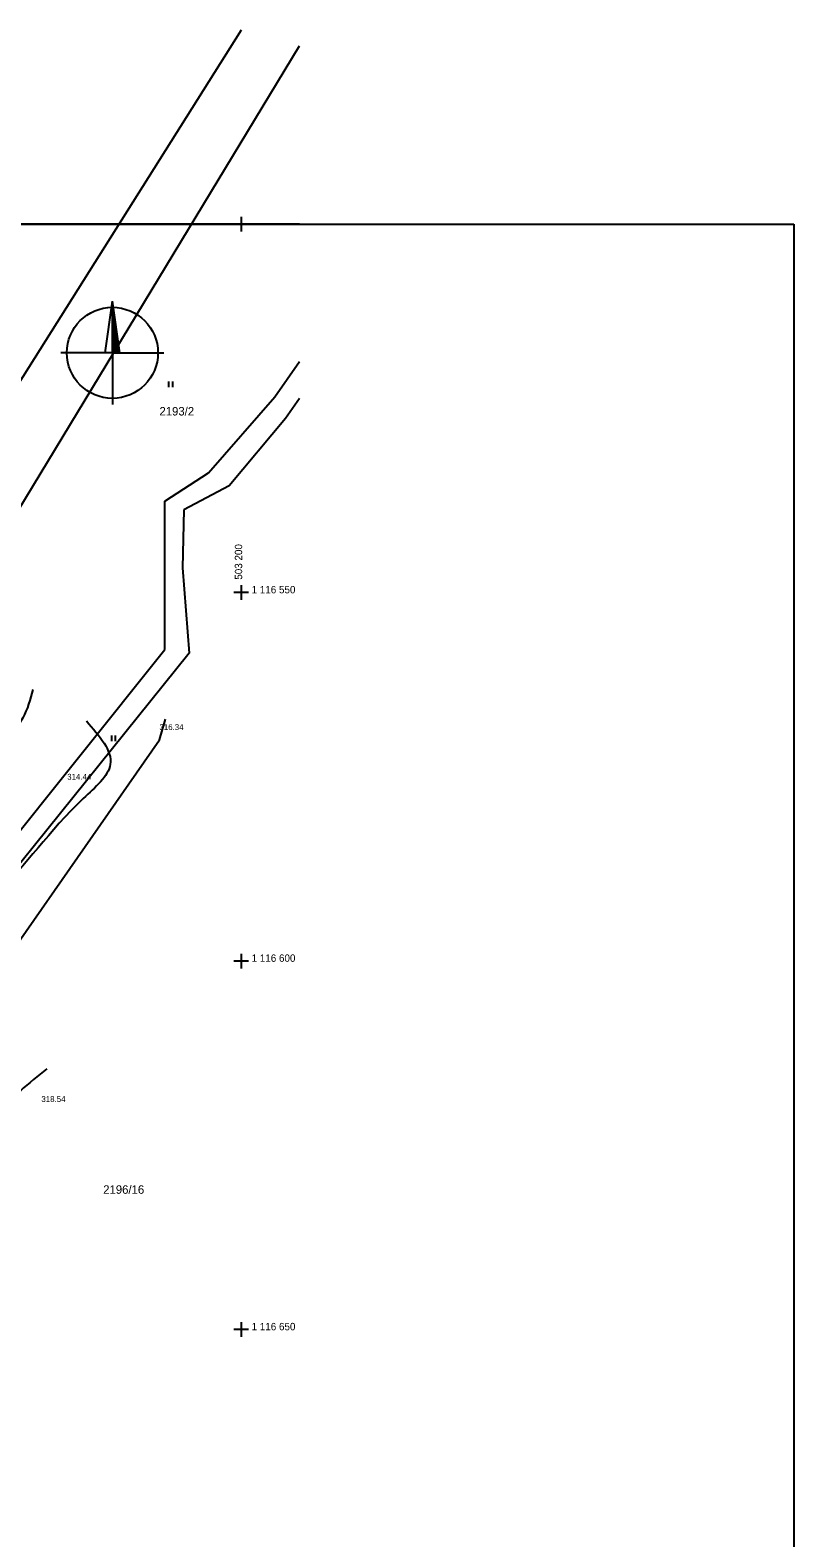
# Model space of a CAD drawing. Extents: x -504375 to -503125, y -1118000 to -1116474.
# Drawn here: x -503228.6 to -503125, y -1116678.3 to -1116473.7 of the extents above; entities that cross this region are included whole.
import ezdxf

# ---------------------------------------------------------------- set-up
doc = ezdxf.new("R2010")
doc.units = 0
for name, color, linetype in [('Druhy povrchů', 7, 'Continuous'), ('Podkladové mapy', 7, 'Continuous'), ('Síť dekadická', 7, 'Continuous'), ('Vrstva 34', 7, 'Continuous'), ('Vrstva 48', 7, 'Continuous'), ('Výšky bodů plotr', 7, 'Continuous')]:
    doc.layers.add(name, color=color, linetype=linetype)

msp = doc.modelspace()

# ---------------------------------------------------------------- linework, layer by layer
at = {"layer": 'Druhy povrchů'}
for p, q in [((-503217.54, -1116570.142), (-503217.54, -1116569.392)), ((-503217.04, -1116570.142), (-503217.04, -1116569.392))]:
    msp.add_line(p, q, dxfattribs=at)
at = {"layer": 'Podkladové mapy'}
for p, q in [((-503200.022, -1116473.684), (-503238.29, -1116534.46)), ((-503230.27, -1116538.88), (-503192.069, -1116475.796)), ((-503195.45, -1116523.45), (-503192.069, -1116518.634)), ((-503209.807, -1116522.114), (-503209.807, -1116521.364)), ((-503209.307, -1116521.364), (-503209.307, -1116522.114)), ((-503204.44, -1116533.76), (-503195.45, -1116523.45)), ((-503192.069, -1116523.684), (-503193.98, -1116526.4)), ((-503193.98, -1116526.4), (-503201.65, -1116535.51)), ((-503210.38, -1116537.61), (-503204.44, -1116533.76)), ((-503201.65, -1116535.51), (-503207.78, -1116538.78)), ((-503210.38, -1116557.71), (-503210.38, -1116537.61)), ((-503207.78, -1116538.78), (-503207.98, -1116546.65)), ((-503207.98, -1116546.65), (-503207.06, -1116558.21)), ((-503233.98, -1116587.25), (-503210.38, -1116557.71)), ((-503207.06, -1116558.21), (-503233.96, -1116591.65))]:
    msp.add_line(p, q, dxfattribs=at)
at = {"layer": 'Síť dekadická'}
msp.add_lwpolyline([(-503125, -1116500), (-503125, -1117000), (-503750, -1117000), (-503750, -1116500)], close=True, dxfattribs=at)
at = {"layer": 'Vrstva 34'}
for p, q in [((-503200, -1116499), (-503200, -1116501)), ((-503199, -1116500), (-503201, -1116500)), ((-503218.473, -1116517.471), (-503217.473, -1116510.471)), ((-503216.473, -1116517.471), (-503217.473, -1116510.471)), ((-503217.473, -1116517.471), (-503217.473, -1116510.471)), ((-503217.473, -1116510.515), (-503217.467, -1116510.515)), ((-503217.473, -1116510.565), (-503217.459, -1116510.565)), ((-503217.473, -1116510.615), (-503217.452, -1116510.615)), ((-503217.473, -1116510.665), (-503217.445, -1116510.665)), ((-503217.473, -1116510.715), (-503217.438, -1116510.715)), ((-503217.473, -1116510.765), (-503217.431, -1116510.765)), ((-503217.473, -1116510.815), (-503217.424, -1116510.815)), ((-503217.473, -1116510.865), (-503217.417, -1116510.865)), ((-503217.473, -1116510.915), (-503217.41, -1116510.915)), ((-503217.473, -1116510.965), (-503217.402, -1116510.965)), ((-503217.473, -1116511.015), (-503217.395, -1116511.015)), ((-503217.473, -1116511.065), (-503217.388, -1116511.065)), ((-503217.473, -1116511.115), (-503217.381, -1116511.115)), ((-503217.473, -1116511.165), (-503217.374, -1116511.165)), ((-503217.473, -1116511.215), (-503217.367, -1116511.215)), ((-503217.473, -1116511.265), (-503217.36, -1116511.265)), ((-503217.473, -1116511.325), (-503217.351, -1116511.325)), ((-503217.473, -1116511.375), (-503217.344, -1116511.375)), ((-503217.473, -1116511.425), (-503217.337, -1116511.425)), ((-503217.473, -1116511.475), (-503217.33, -1116511.475)), ((-503217.473, -1116511.525), (-503217.323, -1116511.525)), ((-503217.473, -1116511.575), (-503217.315, -1116511.575)), ((-503217.473, -1116511.625), (-503217.308, -1116511.625)), ((-503217.473, -1116511.675), (-503217.301, -1116511.675)), ((-503217.473, -1116511.725), (-503217.294, -1116511.725)), ((-503217.473, -1116511.775), (-503217.287, -1116511.775)), ((-503217.473, -1116511.825), (-503217.28, -1116511.825)), ((-503217.473, -1116511.875), (-503217.273, -1116511.875)), ((-503217.473, -1116511.925), (-503217.265, -1116511.925)), ((-503217.473, -1116511.975), (-503217.258, -1116511.975)), ((-503217.473, -1116512.025), (-503217.251, -1116512.025)), ((-503217.473, -1116512.075), (-503217.244, -1116512.075)), ((-503217.473, -1116512.125), (-503217.237, -1116512.125)), ((-503217.473, -1116512.175), (-503217.23, -1116512.175)), ((-503217.473, -1116512.225), (-503217.223, -1116512.225)), ((-503217.473, -1116512.275), (-503217.215, -1116512.275)), ((-503217.473, -1116512.325), (-503217.208, -1116512.325)), ((-503217.473, -1116512.375), (-503217.201, -1116512.375)), ((-503217.473, -1116512.425), (-503217.194, -1116512.425)), ((-503217.473, -1116512.475), (-503217.187, -1116512.475)), ((-503217.473, -1116512.525), (-503217.18, -1116512.525)), ((-503217.473, -1116512.575), (-503217.173, -1116512.575)), ((-503217.473, -1116512.625), (-503217.165, -1116512.625)), ((-503217.473, -1116512.675), (-503217.158, -1116512.675)), ((-503217.473, -1116512.725), (-503217.151, -1116512.725)), ((-503217.473, -1116512.775), (-503217.144, -1116512.775)), ((-503217.473, -1116512.825), (-503217.137, -1116512.825)), ((-503217.473, -1116512.875), (-503217.13, -1116512.875)), ((-503217.473, -1116512.925), (-503217.122, -1116512.925)), ((-503217.473, -1116512.975), (-503217.115, -1116512.975)), ((-503217.473, -1116513.025), (-503217.108, -1116513.025)), ((-503217.473, -1116513.075), (-503217.101, -1116513.075)), ((-503217.473, -1116513.125), (-503217.094, -1116513.125)), ((-503217.473, -1116513.175), (-503217.087, -1116513.175)), ((-503217.473, -1116513.225), (-503217.08, -1116513.225)), ((-503217.473, -1116513.275), (-503217.072, -1116513.275)), ((-503217.473, -1116513.325), (-503217.065, -1116513.325)), ((-503217.473, -1116513.375), (-503217.058, -1116513.375)), ((-503217.473, -1116513.425), (-503217.051, -1116513.425)), ((-503217.473, -1116513.475), (-503217.044, -1116513.475)), ((-503217.473, -1116513.525), (-503217.037, -1116513.525)), ((-503217.473, -1116513.575), (-503217.03, -1116513.575)), ((-503217.473, -1116513.625), (-503217.022, -1116513.625)), ((-503217.473, -1116513.675), (-503217.015, -1116513.675)), ((-503217.473, -1116513.725), (-503217.008, -1116513.725)), ((-503217.473, -1116513.775), (-503217.001, -1116513.775)), ((-503217.473, -1116513.825), (-503216.994, -1116513.825)), ((-503217.473, -1116513.875), (-503216.987, -1116513.875)), ((-503217.473, -1116513.925), (-503216.98, -1116513.925)), ((-503217.473, -1116513.975), (-503216.972, -1116513.975)), ((-503217.473, -1116514.025), (-503216.965, -1116514.025)), ((-503217.473, -1116514.075), (-503216.958, -1116514.075)), ((-503217.473, -1116514.125), (-503216.951, -1116514.125)), ((-503217.473, -1116514.175), (-503216.944, -1116514.175)), ((-503217.473, -1116514.225), (-503216.937, -1116514.225)), ((-503217.473, -1116514.275), (-503216.93, -1116514.275)), ((-503217.473, -1116514.325), (-503216.922, -1116514.325)), ((-503217.473, -1116514.375), (-503216.915, -1116514.375)), ((-503217.473, -1116514.425), (-503216.908, -1116514.425)), ((-503217.473, -1116514.475), (-503216.901, -1116514.475)), ((-503217.473, -1116514.525), (-503216.894, -1116514.525)), ((-503217.473, -1116514.575), (-503216.887, -1116514.575)), ((-503217.473, -1116514.625), (-503216.88, -1116514.625)), ((-503217.473, -1116514.675), (-503216.872, -1116514.675)), ((-503217.473, -1116514.725), (-503216.865, -1116514.725)), ((-503217.473, -1116514.775), (-503216.858, -1116514.775)), ((-503217.473, -1116514.825), (-503216.851, -1116514.825)), ((-503217.473, -1116514.875), (-503216.844, -1116514.875)), ((-503217.473, -1116514.925), (-503216.837, -1116514.925)), ((-503217.473, -1116514.975), (-503216.83, -1116514.975)), ((-503217.473, -1116515.025), (-503216.822, -1116515.025)), ((-503217.473, -1116515.075), (-503216.815, -1116515.075)), ((-503217.473, -1116515.125), (-503216.808, -1116515.125)), ((-503217.473, -1116515.175), (-503216.801, -1116515.175)), ((-503217.473, -1116515.225), (-503216.794, -1116515.225)), ((-503217.473, -1116515.275), (-503216.787, -1116515.275)), ((-503217.473, -1116515.325), (-503216.78, -1116515.325)), ((-503217.473, -1116515.375), (-503216.772, -1116515.375)), ((-503217.473, -1116515.425), (-503216.765, -1116515.425)), ((-503217.473, -1116515.475), (-503216.758, -1116515.475)), ((-503217.473, -1116515.525), (-503216.751, -1116515.525)), ((-503217.473, -1116515.575), (-503216.744, -1116515.575)), ((-503217.473, -1116515.625), (-503216.737, -1116515.625)), ((-503217.473, -1116515.675), (-503216.73, -1116515.675)), ((-503217.473, -1116515.725), (-503216.722, -1116515.725)), ((-503217.473, -1116515.775), (-503216.715, -1116515.775)), ((-503217.473, -1116515.825), (-503216.708, -1116515.825)), ((-503217.473, -1116515.875), (-503216.701, -1116515.875)), ((-503217.473, -1116515.925), (-503216.694, -1116515.925)), ((-503217.473, -1116515.975), (-503216.687, -1116515.975)), ((-503217.473, -1116516.025), (-503216.679, -1116516.025)), ((-503217.473, -1116516.075), (-503216.672, -1116516.075)), ((-503217.473, -1116516.125), (-503216.665, -1116516.125)), ((-503217.473, -1116516.175), (-503216.658, -1116516.175)), ((-503217.473, -1116516.225), (-503216.651, -1116516.225)), ((-503217.473, -1116516.275), (-503216.644, -1116516.275)), ((-503217.473, -1116517.471), (-503224.473, -1116517.471)), ((-503217.473, -1116516.325), (-503216.637, -1116516.325)), ((-503217.473, -1116516.375), (-503216.629, -1116516.375)), ((-503217.473, -1116516.425), (-503216.622, -1116516.425)), ((-503217.473, -1116516.475), (-503216.615, -1116516.475)), ((-503217.473, -1116516.525), (-503216.608, -1116516.525)), ((-503217.473, -1116516.575), (-503216.601, -1116516.575)), ((-503217.473, -1116516.625), (-503216.594, -1116516.625)), ((-503217.473, -1116516.675), (-503216.587, -1116516.675)), ((-503217.473, -1116516.725), (-503216.579, -1116516.725)), ((-503217.473, -1116516.775), (-503216.572, -1116516.775)), ((-503217.473, -1116516.825), (-503216.565, -1116516.825)), ((-503217.473, -1116516.875), (-503216.558, -1116516.875)), ((-503217.473, -1116516.925), (-503216.551, -1116516.925)), ((-503217.473, -1116516.975), (-503216.544, -1116516.975)), ((-503217.473, -1116517.025), (-503216.537, -1116517.025)), ((-503217.473, -1116517.075), (-503216.529, -1116517.075)), ((-503217.473, -1116517.125), (-503216.522, -1116517.125)), ((-503217.473, -1116517.175), (-503216.515, -1116517.175)), ((-503217.473, -1116517.225), (-503216.508, -1116517.225)), ((-503217.473, -1116517.275), (-503216.501, -1116517.275)), ((-503217.473, -1116517.325), (-503216.494, -1116517.325)), ((-503217.473, -1116517.375), (-503216.487, -1116517.375)), ((-503217.473, -1116517.425), (-503216.479, -1116517.425)), ((-503217.473, -1116517.471), (-503217.473, -1116524.471)), ((-503217.473, -1116517.471), (-503216.473, -1116517.471)), ((-503216.473, -1116517.471), (-503210.473, -1116517.471)), ((-503200, -1116549), (-503200, -1116551)), ((-503199, -1116550), (-503201, -1116550)), ((-503199, -1116600), (-503201, -1116600)), ((-503200, -1116599), (-503200, -1116601)), ((-503200, -1116649), (-503200, -1116651)), ((-503199, -1116650), (-503201, -1116650))]:
    msp.add_line(p, q, dxfattribs=at)
msp.add_lwpolyline([(-503192.069, -1116500), (-503591.069, -1116500)], dxfattribs=at)
msp.add_circle((-503217.473, -1116517.47), 6.18, dxfattribs=at)
at = {"layer": 'Vrstva 48'}
msp.add_lwpolyline([(-503300.434, -1116681.166), (-503296.556, -1116668.103), (-503294.8, -1116667.049), (-503286.048, -1116656.931), (-503285.304, -1116656.071), (-503279.91, -1116655.384), (-503275.719, -1116650.391), (-503271.777, -1116639.009), (-503265.04, -1116633.168), (-503262.143, -1116630.656), (-503250.15, -1116616.106), (-503234.98, -1116601.014), (-503231.273, -1116598.925), (-503211.098, -1116569.991), (-503210.256, -1116567.168)], dxfattribs=at)
for points in [[(-503228.261, -1116563.145), (-503229.645, -1116567.016), (-503233.265, -1116571.228), (-503245.688, -1116584.541), (-503247.935, -1116586.867), (-503252.973, -1116594.854), (-503254.135, -1116607.338), (-503261.55, -1116616.428), (-503262.857, -1116617.898), (-503273.652, -1116628.941), (-503288.12, -1116641.769), (-503294.834, -1116647.413), (-503299.542, -1116653.756), (-503302.433, -1116657.068), (-503311.897, -1116663.915), (-503313.227, -1116667.667), (-503316.736, -1116674.505), (-503325.627, -1116690.3), (-503328.511, -1116695.009), (-503335.94, -1116707.278), (-503351.034, -1116723.382), (-503365.126, -1116737.245), (-503372.674, -1116748.782), (-503373.925, -1116753.16), (-503378.551, -1116760.666), (-503382.552, -1116767.547), (-503390.579, -1116780.739), (-503398.79, -1116793.818), (-503400.908, -1116797.881), (-503402.495, -1116807.226), (-503404.198, -1116812.046), (-503412.471, -1116822.312), (-503418.387, -1116829.995), (-503420.024, -1116835.788), (-503425.814, -1116843.155), (-503430.336, -1116857.921), (-503433.683, -1116863.223), (-503434.674, -1116865.019), (-503440.926, -1116880.75), (-503445.259, -1116893.88)], [(-503220.996, -1116567.416), (-503217.756, -1116573.319), (-503221.427, -1116577.942), (-503233.269, -1116590.886), (-503241.732, -1116597.917), (-503258.62, -1116620.268), (-503262.643, -1116624.456), (-503264.199, -1116625.94)], [(-503226.376, -1116614.632), (-503233.107, -1116620.885), (-503240.101, -1116634.653), (-503252.255, -1116650.684), (-503264.774, -1116665.135), (-503266.507, -1116667.062), (-503278.833, -1116680.261), (-503283.648, -1116688.161), (-503287.693, -1116698.856)]]:
    msp.add_spline(points, degree=3, dxfattribs=at)

# ---------------------------------------------------------------- texts
at = {"layer": 'Podkladové mapy'}
for s, p in [('2193/2', (-503211.09, -1116525.972)), ('2196/16', (-503218.72, -1116631.581))]:
    msp.add_text(s, height=1.15, dxfattribs=at).set_placement(p)
at = {"layer": 'Vrstva 34'}
msp.add_text('503 200', height=1, rotation=90, dxfattribs=at).set_placement((-503199.863, -1116548.255))
for s, p in [('1 116 550', (-503198.586, -1116550.102)), ('1 116 600', (-503198.586, -1116600.102)), ('1 116 650', (-503198.586, -1116650.102))]:
    msp.add_text(s, height=1, dxfattribs=at).set_placement(p)
at = {"layer": 'Výšky bodů plotr'}
for s, p in [('316.34 ', (-503211.09, -1116568.66)), ('314.44 ', (-503223.61, -1116575.4)), ('318.54 ', (-503227.11, -1116619.13))]:
    msp.add_text(s, height=0.8, dxfattribs=at).set_placement(p)

doc.saveas('drawing.dxf')
